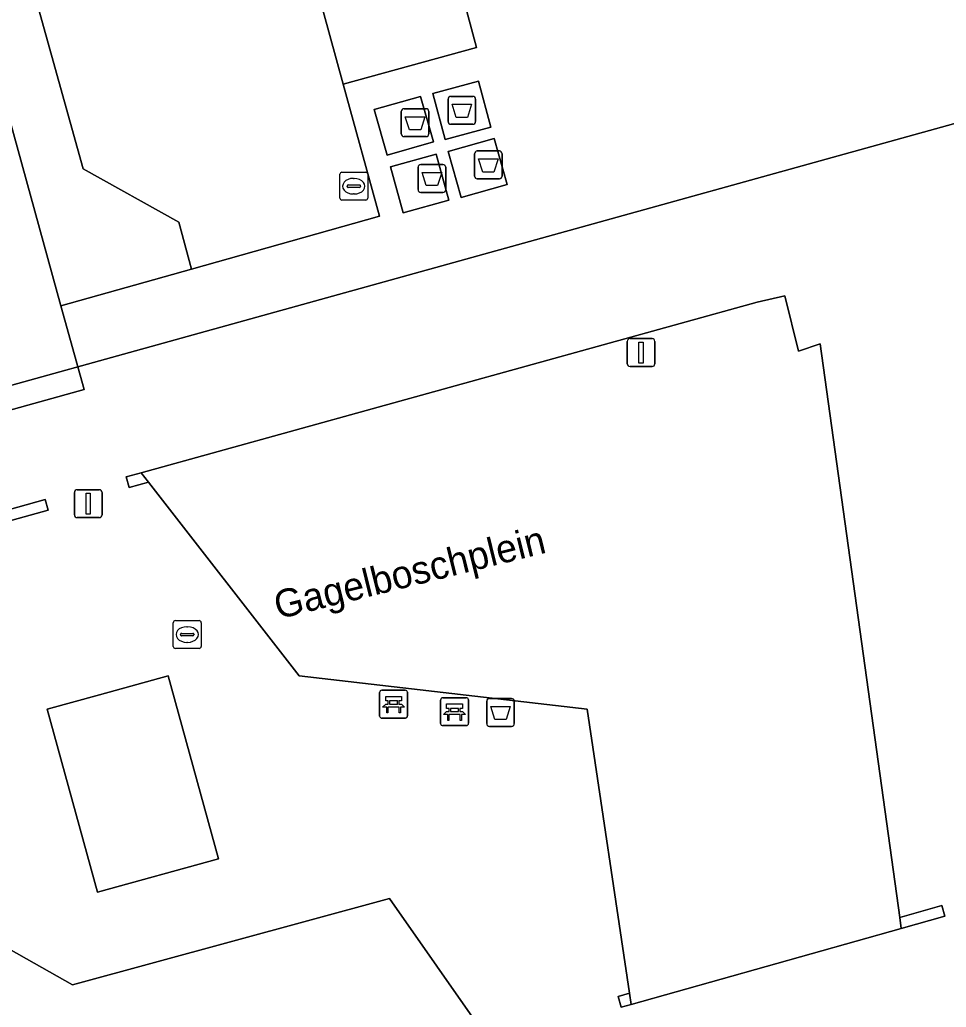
# Model space of a CAD drawing. Extents: x 159053 to 160042, y 380449 to 381423.
# Drawn here: x 159156.36 to 159189.59, y 381123.1 to 381158.52 of the extents above; entities that cross this region are included whole.
import ezdxf

# ---------------------------------------------------------------- set-up
doc = ezdxf.new("R2010")
doc.units = 0
for name, color, linetype in [('IMGEO_Afval_apart_plaats', 7, 'Continuous'), ('IMGEO_Afvalbak', 7, 'Continuous'), ('IMGEO_Bank', 7, 'Continuous'), ('IMGEO_Brandkraan', 7, 'Continuous'), ('IMGEO_Groenvoorziening', 7, 'Continuous'), ('IMGEO_Lichtmast', 7, 'Continuous'), ('IMGEO_Muur', 7, 'Continuous'), ('IMGEO_Openbare_ruimte_label', 7, 'Continuous'), ('IMGEO_Pand', 7, 'Continuous'), ('IMGEO_Pand_overbouw', 7, 'Continuous'), ('IMGEO_Pand_vergunning_verleend', 7, 'Continuous'), ('IMGEO_Parkeervlak_open', 7, 'Continuous'), ('IMGEO_Rijbaan_lokaal_open', 7, 'Continuous'), ('IMGEO_Voetpad_gesloten', 7, 'Continuous'), ('IMGEO_Voetpad_open', 7, 'Continuous')]:
    doc.layers.add(name, color=color, linetype=linetype)

msp = doc.modelspace()

# ---------------------------------------------------------------- linework, layer by layer
at = {"layer": 'IMGEO_Afval_apart_plaats'}
for p, q in [((159171.819, 381155.769), (159172.609, 381155.769)), ((159172.609, 381155.769), (159171.819, 381155.769)), ((159171.719, 381154.869), (159171.719, 381155.669)), ((159171.719, 381155.669), (159171.719, 381154.869)), ((159172.709, 381155.669), (159172.709, 381154.869)), ((159172.709, 381154.869), (159172.709, 381155.669)), ((159170.041, 381154.425), (159170.041, 381155.225)), ((159170.041, 381155.225), (159170.041, 381154.425)), ((159170.141, 381155.325), (159170.931, 381155.325)), ((159170.931, 381155.325), (159170.141, 381155.325)), ((159171.031, 381155.225), (159171.031, 381154.425)), ((159171.031, 381154.425), (159171.031, 381155.225)), ((159172.609, 381154.769), (159171.819, 381154.769)), ((159171.819, 381154.769), (159172.609, 381154.769)), ((159170.931, 381154.325), (159170.141, 381154.325)), ((159170.141, 381154.325), (159170.931, 381154.325)), ((159172.669, 381152.91), (159172.669, 381153.71)), ((159172.669, 381153.71), (159172.669, 381152.91)), ((159172.769, 381153.81), (159173.559, 381153.81)), ((159173.559, 381153.81), (159172.769, 381153.81)), ((159173.659, 381153.71), (159173.659, 381152.91)), ((159173.659, 381152.91), (159173.659, 381153.71)), ((159170.645, 381152.424), (159170.645, 381153.224)), ((159170.645, 381153.224), (159170.645, 381152.424)), ((159170.745, 381153.324), (159171.535, 381153.324)), ((159171.535, 381153.324), (159170.745, 381153.324)), ((159171.635, 381153.224), (159171.635, 381152.424)), ((159171.635, 381152.424), (159171.635, 381153.224)), ((159173.559, 381152.81), (159172.769, 381152.81)), ((159172.769, 381152.81), (159173.559, 381152.81)), ((159171.535, 381152.324), (159170.745, 381152.324)), ((159170.745, 381152.324), (159171.535, 381152.324))]:
    msp.add_line(p, q, dxfattribs=at)
for points in [[(159171.862, 381155.483), (159172.566, 381155.483), (159172.417, 381155.013), (159172.011, 381155.013), (159171.862, 381155.483)], [(159170.184, 381155.039), (159170.888, 381155.039), (159170.739, 381154.569), (159170.333, 381154.569), (159170.184, 381155.039)], [(159172.812, 381153.524), (159173.516, 381153.524), (159173.367, 381153.054), (159172.961, 381153.054), (159172.812, 381153.524)], [(159170.788, 381153.038), (159171.492, 381153.038), (159171.343, 381152.568), (159170.937, 381152.568), (159170.788, 381153.038)]]:
    msp.add_lwpolyline(points, dxfattribs=at)
for centre, start, end in [((159171.819, 381155.669), 90, 180), ((159171.819, 381155.669), 90, 180), ((159172.609, 381155.669), 0, 90), ((159172.609, 381155.669), 360, 90), ((159170.141, 381155.225), 90, 180), ((159170.141, 381155.225), 90, 180), ((159170.931, 381155.225), 0, 90), ((159170.931, 381155.225), 360, 90), ((159171.819, 381154.869), 180, 270), ((159171.819, 381154.869), 180, 270), ((159172.609, 381154.869), 270, 0), ((159172.609, 381154.869), 270, 0), ((159170.141, 381154.425), 180, 270), ((159170.141, 381154.425), 180, 270), ((159170.931, 381154.425), 270, 0), ((159170.931, 381154.425), 270, 0), ((159172.769, 381153.71), 90, 180), ((159172.769, 381153.71), 90, 180), ((159173.559, 381153.71), 0, 90), ((159173.559, 381153.71), 360, 90), ((159170.745, 381153.224), 90, 180), ((159170.745, 381153.224), 90, 180), ((159171.535, 381153.224), 0, 90), ((159171.535, 381153.224), 360, 90), ((159172.769, 381152.91), 180, 270), ((159172.769, 381152.91), 180, 270), ((159173.559, 381152.91), 270, 0), ((159173.559, 381152.91), 270, 0), ((159170.745, 381152.424), 180, 270), ((159170.745, 381152.424), 180, 270), ((159171.535, 381152.424), 270, 0), ((159171.535, 381152.424), 270, 0)]:
    msp.add_arc(centre, 0.1, start, end, dxfattribs=at)
at = {"layer": 'IMGEO_Afvalbak'}
for p, q in [((159173.206, 381134.175), (159173.996, 381134.175)), ((159173.996, 381134.175), (159173.206, 381134.175)), ((159173.106, 381133.275), (159173.106, 381134.075)), ((159173.106, 381134.075), (159173.106, 381133.275)), ((159174.096, 381134.075), (159174.096, 381133.275)), ((159174.096, 381133.275), (159174.096, 381134.075)), ((159173.996, 381133.175), (159173.206, 381133.175)), ((159173.206, 381133.175), (159173.996, 381133.175))]:
    msp.add_line(p, q, dxfattribs=at)
msp.add_lwpolyline([(159173.249, 381133.889), (159173.953, 381133.889), (159173.804, 381133.419), (159173.398, 381133.419), (159173.249, 381133.889)], dxfattribs=at)
for centre, start, end in [((159173.206, 381134.075), 90, 180), ((159173.206, 381134.075), 90, 180), ((159173.996, 381134.075), 0, 90), ((159173.996, 381134.075), 360, 90), ((159173.206, 381133.275), 180, 270), ((159173.206, 381133.275), 180, 270), ((159173.996, 381133.275), 270, 0), ((159173.996, 381133.275), 270, 0)]:
    msp.add_arc(centre, 0.1, start, end, dxfattribs=at)
at = {"layer": 'IMGEO_Bank'}
for p, q in [((159169.34, 381134.471), (159170.181, 381134.471)), ((159170.181, 381134.471), (159169.34, 381134.471)), ((159169.265, 381133.546), (159169.265, 381134.387)), ((159169.265, 381134.387), (159169.265, 381133.546)), ((159169.906, 381134.089), (159169.624, 381134.089)), ((159170.265, 381134.396), (159170.265, 381133.555)), ((159170.265, 381133.555), (159170.265, 381134.396)), ((159171.452, 381133.278), (159171.452, 381134.119)), ((159171.452, 381134.119), (159171.452, 381133.278)), ((159171.527, 381134.203), (159172.368, 381134.203)), ((159172.368, 381134.203), (159171.527, 381134.203)), ((159172.452, 381134.128), (159172.452, 381133.287)), ((159172.452, 381133.287), (159172.452, 381134.128)), ((159169.962, 381133.869), (159169.569, 381133.869)), ((159169.574, 381133.977), (159169.574, 381134.083)), ((159169.618, 381134.083), (159169.618, 381133.977)), ((159169.624, 381133.971), (159169.906, 381133.971)), ((159169.912, 381133.977), (159169.912, 381134.083)), ((159169.956, 381134.083), (159169.956, 381133.977)), ((159171.761, 381133.709), (159171.761, 381133.815)), ((159171.805, 381133.815), (159171.805, 381133.709)), ((159172.093, 381133.821), (159171.811, 381133.821)), ((159172.099, 381133.709), (159172.099, 381133.815)), ((159172.143, 381133.815), (159172.143, 381133.709)), ((159170.19, 381133.471), (159169.349, 381133.471)), ((159169.349, 381133.471), (159170.19, 381133.471)), ((159172.149, 381133.601), (159171.756, 381133.601)), ((159171.811, 381133.703), (159172.093, 381133.703)), ((159172.377, 381133.203), (159171.536, 381133.203)), ((159171.536, 381133.203), (159172.377, 381133.203))]:
    msp.add_line(p, q, dxfattribs=at)
for points in [[(159169.568, 381134.089), (159169.482, 381134.089), (159169.482, 381134.25), (159170.045, 381134.25), (159170.045, 381134.089), (159169.962, 381134.089)], [(159169.512, 381133.869), (159169.37, 381133.869), (159169.482, 381133.971), (159169.568, 381133.971)], [(159169.562, 381133.862), (159169.562, 381133.655), (159169.519, 381133.655), (159169.519, 381133.862)], [(159169.962, 381133.971), (159170.045, 381133.971), (159170.157, 381133.869), (159170.018, 381133.869)], [(159170.012, 381133.862), (159170.012, 381133.655), (159169.968, 381133.655), (159169.968, 381133.862)], [(159171.755, 381133.821), (159171.669, 381133.821), (159171.669, 381133.982), (159172.232, 381133.982), (159172.232, 381133.821), (159172.149, 381133.821)], [(159171.699, 381133.601), (159171.557, 381133.601), (159171.669, 381133.703), (159171.755, 381133.703)], [(159171.749, 381133.594), (159171.749, 381133.387), (159171.706, 381133.387), (159171.706, 381133.594)], [(159172.149, 381133.703), (159172.232, 381133.703), (159172.344, 381133.601), (159172.205, 381133.601)], [(159172.199, 381133.594), (159172.199, 381133.387), (159172.155, 381133.387), (159172.155, 381133.594)]]:
    msp.add_lwpolyline(points, dxfattribs=at)
for centre, radius, start, end in [((159169.343, 381134.393), 0.0779, 92.4484, 184.2845), ((159169.343, 381134.393), 0.0779, 92.4484, 184.2845), ((159170.187, 381134.393), 0.0779, 2.4484, 94.2845), ((159170.187, 381134.393), 0.0779, 2.4484, 94.2845), ((159169.567, 381134.082), 0.00671, 2.8957, 87.1043), ((159169.624, 381134.082), 0.00671, 92.8957, 177.1043), ((159169.906, 381134.082), 0.00671, 2.8957, 87.1043), ((159169.963, 381134.082), 0.00671, 92.8957, 177.1043), ((159171.53, 381134.125), 0.0779, 92.4484, 184.2845), ((159171.53, 381134.125), 0.0779, 92.4484, 184.2845), ((159172.374, 381134.125), 0.0779, 2.4484, 94.2845), ((159172.374, 381134.125), 0.0779, 2.4484, 94.2845), ((159169.512, 381133.862), 0.00671, 2.8957, 87.1043), ((159169.569, 381133.862), 0.00671, 92.8957, 177.1043), ((159169.567, 381133.978), 0.00671, 272.8957, 357.1043), ((159169.624, 381133.978), 0.00671, 182.8957, 267.1043), ((159169.906, 381133.978), 0.00671, 272.8957, 357.1043), ((159169.963, 381133.978), 0.00671, 182.8957, 267.1043), ((159169.961, 381133.862), 0.00671, 2.8957, 87.1043), ((159170.018, 381133.862), 0.00671, 92.8957, 177.1043), ((159171.754, 381133.814), 0.00671, 2.8957, 87.1043), ((159171.811, 381133.814), 0.00671, 92.8957, 177.1043), ((159172.093, 381133.814), 0.00671, 2.8957, 87.1043), ((159172.15, 381133.814), 0.00671, 92.8957, 177.1043), ((159169.343, 381133.549), 0.0779, 182.4484, 274.2845), ((159169.343, 381133.549), 0.0779, 182.4484, 274.2845), ((159170.187, 381133.549), 0.0779, 272.4484, 4.2845), ((159170.187, 381133.549), 0.0779, 272.4484, 4.2845), ((159171.699, 381133.594), 0.00671, 2.8957, 87.1043), ((159171.756, 381133.594), 0.00671, 92.8957, 177.1043), ((159171.754, 381133.71), 0.00671, 272.8957, 357.1043), ((159171.811, 381133.71), 0.00671, 182.8957, 267.1043), ((159172.093, 381133.71), 0.00671, 272.8957, 357.1043), ((159172.15, 381133.71), 0.00671, 182.8957, 267.1043), ((159172.148, 381133.594), 0.00671, 2.8957, 87.1043), ((159172.205, 381133.594), 0.00671, 92.8957, 177.1043), ((159171.53, 381133.281), 0.0779, 182.4484, 274.2845), ((159171.53, 381133.281), 0.0779, 182.4484, 274.2845), ((159172.374, 381133.281), 0.0779, 272.4484, 4.2845), ((159172.374, 381133.281), 0.0779, 272.4484, 4.2845)]:
    msp.add_arc(centre, radius, start, end, dxfattribs=at)
at = {"layer": 'IMGEO_Brandkraan'}
for p, q in [((159167.838, 381152.121), (159167.838, 381152.973)), ((159167.913, 381153.047), (159168.765, 381153.047)), ((159168.839, 381152.973), (159168.839, 381152.121)), ((159168.097, 381152.541), (159168.097, 381152.553)), ((159168.535, 381152.504), (159168.137, 381152.504)), ((159168.14, 381152.59), (159168.538, 381152.59)), ((159168.326, 381152.827), (159168.351, 381152.827)), ((159168.581, 381152.553), (159168.581, 381152.541)), ((159168.349, 381152.267), (159168.324, 381152.267)), ((159168.765, 381152.047), (159167.913, 381152.047)), ((159161.939, 381136.968), (159162.791, 381136.968)), ((159161.864, 381136.042), (159161.864, 381136.894)), ((159162.352, 381136.748), (159162.377, 381136.748)), ((159162.865, 381136.894), (159162.865, 381136.042)), ((159162.123, 381136.462), (159162.123, 381136.474)), ((159162.561, 381136.425), (159162.163, 381136.425)), ((159162.166, 381136.511), (159162.564, 381136.511)), ((159162.607, 381136.474), (159162.607, 381136.462)), ((159162.791, 381135.968), (159161.939, 381135.968)), ((159162.375, 381136.188), (159162.35, 381136.188))]:
    msp.add_line(p, q, dxfattribs=at)
for points in [[(159167.838, 381152.121), (159167.838, 381152.973)], [(159167.913, 381153.047), (159168.765, 381153.047)], [(159168.839, 381152.973), (159168.839, 381152.121)], [(159168.765, 381152.047), (159167.913, 381152.047)], [(159161.939, 381136.968), (159162.791, 381136.968)], [(159161.864, 381136.042), (159161.864, 381136.894)], [(159162.865, 381136.894), (159162.865, 381136.042)], [(159162.791, 381135.968), (159161.939, 381135.968)]]:
    msp.add_lwpolyline(points, dxfattribs=at)
for centre, radius, start, end in [((159167.915, 381152.971), 0.0765, 91.552, 178.448), ((159167.915, 381152.971), 0.0765, 91.552, 178.448), ((159168.763, 381152.971), 0.0765, 1.552, 88.448), ((159168.763, 381152.971), 0.0765, 1.552, 88.448), ((159168.137, 381152.55), 0.0403, 85.8775, 175.7526), ((159168.134, 381152.54), 0.0366, 178.938, 274.7102), ((159168.538, 381152.547), 0.043, 264.8664, 352.4533), ((159168.542, 381152.552), 0.0386, 1.7309, 96.639), ((159167.915, 381152.123), 0.0765, 181.552, 268.448), ((159167.915, 381152.123), 0.0765, 181.552, 268.448), ((159168.763, 381152.123), 0.0765, 271.552, 358.448), ((159168.763, 381152.123), 0.0765, 271.552, 358.448), ((159161.941, 381136.892), 0.0765, 91.552, 178.448), ((159161.941, 381136.892), 0.0765, 91.552, 178.448), ((159162.789, 381136.892), 0.0765, 1.552, 88.448), ((159162.789, 381136.892), 0.0765, 1.552, 88.448), ((159162.163, 381136.471), 0.0403, 85.8775, 175.7526), ((159162.16, 381136.461), 0.0366, 178.938, 274.7102), ((159162.564, 381136.468), 0.043, 264.8664, 352.4533), ((159162.568, 381136.473), 0.0386, 1.7309, 96.639), ((159161.941, 381136.044), 0.0765, 181.552, 268.448), ((159161.941, 381136.044), 0.0765, 181.552, 268.448), ((159162.789, 381136.044), 0.0765, 271.552, 358.448), ((159162.789, 381136.044), 0.0765, 271.552, 358.448)]:
    msp.add_arc(centre, radius, start, end, dxfattribs=at)
for centre, major_axis, ratio, start_param, end_param in [((159168.325, 381152.547), (-0.387, 0.002), 0.722429, 4.712389, 7.853982), ((159168.35, 381152.547), (-0.39, 0.002), 0.717154, 1.570796, 4.712389), ((159162.351, 381136.468), (-0.387, 0.002), 0.722429, 4.712389, 7.853982), ((159162.376, 381136.468), (-0.39, 0.002), 0.717154, 1.570796, 4.712389)]:
    msp.add_ellipse(centre, major_axis=major_axis, ratio=ratio, start_param=start_param, end_param=end_param, dxfattribs=at)
at = {"layer": 'IMGEO_Groenvoorziening'}
msp.add_lwpolyline([(159121.982, 381156.173), (159127.859, 381157.764), (159125.308, 381167.186), (159149.74, 381174.045), (159151.875, 381166.058), (159152.853, 381166.328), (159154.809, 381166.867), (159158.633, 381153.175), (159162.065, 381151.254), (159162.515, 381149.573), (159169.259, 381151.47), (159167.96, 381156.207), (159163.076, 381174.02), (159172.151, 381181.759)], dxfattribs=at)
for points in [[(159185.063, 381146.894), (159184.287, 381146.632), (159183.8, 381148.611), (159182.803, 381148.391), (159160.708, 381142.27), (159160.973, 381141.929), (159166.375, 381134.982), (159176.706, 381133.787), (159178.227, 381123.602), (159178.286, 381123.204), (159187.976, 381125.924), (159187.92, 381126.324)], [(159173.017, 381122.146), (159169.622, 381127.006), (159158.252, 381123.901), (159154.58, 381125.969), (159142.499, 381121.107), (159142.126, 381120.957), (159144.125, 381113.742), (159173.26, 381121.799)]]:
    msp.add_lwpolyline(points, close=True, dxfattribs=at)
at = {"layer": 'IMGEO_Lichtmast'}
for p, q in [((159178.147, 381146.181), (159178.147, 381146.981)), ((159178.147, 381146.981), (159178.147, 381146.181)), ((159178.247, 381147.081), (159179.037, 381147.081)), ((159179.037, 381147.081), (159178.247, 381147.081)), ((159179.137, 381146.981), (159179.137, 381146.181)), ((159179.137, 381146.181), (159179.137, 381146.981)), ((159179.037, 381146.081), (159178.247, 381146.081)), ((159178.247, 381146.081), (159179.037, 381146.081)), ((159158.318, 381140.763), (159158.318, 381141.563)), ((159158.318, 381141.563), (159158.318, 381140.763)), ((159158.418, 381141.663), (159159.208, 381141.663)), ((159159.208, 381141.663), (159158.418, 381141.663)), ((159159.308, 381141.563), (159159.308, 381140.763)), ((159159.308, 381140.763), (159159.308, 381141.563)), ((159159.208, 381140.663), (159158.418, 381140.663)), ((159158.418, 381140.663), (159159.208, 381140.663))]:
    msp.add_line(p, q, dxfattribs=at)
for points in [[(159178.567, 381146.956), (159178.717, 381146.956), (159178.717, 381146.206), (159178.567, 381146.206), (159178.567, 381146.956)], [(159158.738, 381141.538), (159158.888, 381141.538), (159158.888, 381140.788), (159158.738, 381140.788), (159158.738, 381141.538)]]:
    msp.add_lwpolyline(points, dxfattribs=at)
for centre, start, end in [((159178.247, 381146.981), 90, 180), ((159178.247, 381146.981), 90, 180), ((159179.037, 381146.981), 0, 90), ((159179.037, 381146.981), 360, 90), ((159178.247, 381146.181), 180, 270), ((159178.247, 381146.181), 180, 270), ((159179.037, 381146.181), 270, 0), ((159179.037, 381146.181), 270, 0), ((159158.418, 381141.563), 90, 180), ((159158.418, 381141.563), 90, 180), ((159159.208, 381141.563), 0, 90), ((159159.208, 381141.563), 360, 90), ((159158.418, 381140.763), 180, 270), ((159158.418, 381140.763), 180, 270), ((159159.208, 381140.763), 270, 0), ((159159.208, 381140.763), 270, 0)]:
    msp.add_arc(centre, 0.1, start, end, dxfattribs=at)
at = {"layer": 'IMGEO_Muur'}
for points in [[(159160.708, 381142.27), (159160.178, 381142.122), (159160.285, 381141.737), (159160.973, 381141.929)], [(159154.567, 381140.146), (159157.376, 381140.928), (159157.269, 381141.313), (159154.608, 381140.573)], [(159187.976, 381125.924), (159189.542, 381126.364), (159189.434, 381126.749), (159187.92, 381126.324)], [(159178.227, 381123.602), (159177.82, 381123.488), (159177.928, 381123.103), (159178.286, 381123.204)]]:
    msp.add_lwpolyline(points, close=True, dxfattribs=at)
at = {"layer": 'IMGEO_Pand'}
msp.add_lwpolyline([(159161.678, 381134.985), (159159.218, 381134.307), (159157.337, 381133.789), (159159.144, 381127.23), (159163.485, 381128.427)], close=True, dxfattribs=at)
at = {"layer": 'IMGEO_Pand_overbouw'}
msp.add_lwpolyline([(159249.617, 381146.417), (159253.067, 381147.375), (159252.059, 381151.007), (159248.609, 381150.05), (159244.524, 381164.774), (159216.821, 381157.087), (159215.484, 381161.905), (159146.712, 381142.823), (159144.149, 381142.112), (159127.074, 381137.375), (159127.322, 381136.481), (159127.96, 381134.183), (159128.847, 381130.986), (159129.855, 381127.353), (159132.702, 381117.091), (159133.413, 381114.528), (159135.79, 381105.961), (159251.903, 381138.179)], close=True, dxfattribs=at)
at = {"layer": 'IMGEO_Pand_vergunning_verleend'}
msp.add_lwpolyline([(159251.903, 381138.179), (159135.79, 381105.961), (159133.413, 381114.528), (159130.137, 381113.619), (159129.426, 381116.182), (159132.702, 381117.091), (159129.855, 381127.353), (159126.405, 381126.396), (159125.397, 381130.029), (159128.847, 381130.986), (159127.074, 381137.375), (159144.149, 381142.112), (159143.24, 381145.388), (159145.803, 381146.1), (159146.712, 381142.823), (159215.484, 381161.905), (159216.821, 381157.087), (159244.524, 381164.774), (159248.609, 381150.05), (159252.059, 381151.007), (159253.067, 381147.375), (159249.617, 381146.417)], close=True, dxfattribs=at)
at = {"layer": 'IMGEO_Parkeervlak_open'}
msp.add_lwpolyline([(159175.262, 381178.12), (159172.151, 381181.759), (159163.076, 381174.02), (159167.96, 381156.207), (159172.738, 381157.517), (159168.774, 381172.342), (159169.083, 381172.617)], close=True, dxfattribs=at)
at = {"layer": 'IMGEO_Rijbaan_lokaal_open'}
msp.add_lwpolyline([(159168.774, 381172.342), (159172.738, 381157.517), (159167.96, 381156.207), (159169.259, 381151.47), (159162.515, 381149.573), (159157.836, 381148.256), (159158.67, 381145.252), (159127.838, 381136.682)], dxfattribs=at)
for points in [[(159173.254, 381154.667), (159171.619, 381154.225), (159171.174, 381155.871), (159172.809, 381156.313)], [(159171.199, 381154.132), (159169.535, 381153.662), (159169.073, 381155.297), (159170.737, 381155.767)], [(159173.835, 381152.606), (159172.186, 381152.139), (159171.719, 381153.788), (159173.368, 381154.255)], [(159171.748, 381152.043), (159170.11, 381151.595), (159169.659, 381153.245), (159171.297, 381153.693)], [(159187.92, 381126.324), (159189.434, 381126.749), (159189.542, 381126.364), (159187.976, 381125.924), (159178.286, 381123.204), (159177.928, 381123.103), (159177.82, 381123.488), (159178.227, 381123.602), (159176.706, 381133.787), (159166.375, 381134.982), (159160.973, 381141.929), (159160.285, 381141.737), (159160.178, 381142.122), (159160.708, 381142.27), (159182.803, 381148.391), (159183.8, 381148.611), (159184.287, 381146.632), (159185.063, 381146.894)], [(159153.521, 381129.277), (159141.196, 381125.842), (159141.428, 381125.001), (159141.043, 381124.894), (159140.81, 381125.734), (159137.983, 381135.948), (159154.608, 381140.573), (159157.269, 381141.313), (159157.376, 381140.928), (159154.567, 381140.146)], [(159163.485, 381128.427), (159159.144, 381127.23), (159157.337, 381133.789), (159159.218, 381134.307), (159161.678, 381134.985)], [(159173.017, 381122.146), (159174.032, 381122.427), (159174.138, 381122.041), (159173.26, 381121.799), (159144.125, 381113.742), (159142.126, 381120.957), (159141.872, 381121.873), (159142.257, 381121.98), (159142.499, 381121.107), (159154.58, 381125.969), (159158.252, 381123.901), (159169.622, 381127.006)]]:
    msp.add_lwpolyline(points, close=True, dxfattribs=at)
at = {"layer": 'IMGEO_Voetpad_gesloten'}
for points in [[(159172.809, 381156.313), (159171.174, 381155.871), (159171.619, 381154.225), (159173.254, 381154.667)], [(159170.737, 381155.767), (159169.073, 381155.297), (159169.535, 381153.662), (159171.199, 381154.132)], [(159173.368, 381154.255), (159171.719, 381153.788), (159172.186, 381152.139), (159173.835, 381152.606)], [(159171.297, 381153.693), (159169.659, 381153.245), (159170.11, 381151.595), (159171.748, 381152.043)]]:
    msp.add_lwpolyline(points, close=True, dxfattribs=at)
at = {"layer": 'IMGEO_Voetpad_open'}
for points in [[(159158.67, 381145.252), (159157.836, 381148.256), (159152.853, 381166.328), (159151.875, 381166.058), (159149.74, 381174.045), (159125.308, 381167.186), (159127.859, 381157.764), (159130.025, 381158.35), (159128.03, 381165.753), (159148.439, 381171.433), (159150.512, 381163.915), (159150.446, 381163.897), (159155.464, 381145.813), (159135.221, 381140.226), (159134.583, 381142.54), (159123.394, 381139.418), (159123.313, 381139.396), (159124.153, 381136.349), (159124.172, 381136.281)], [(159172.192, 381030.266), (159168.355, 381029.191), (159166.428, 381036.194), (159165.838, 381038.326), (159160.631, 381057.094), (159160.173, 381058.899), (159151.749, 381089.223), (159151.24, 381091.03), (159149.2, 381098.326), (159146.475, 381107.584), (159144.715, 381107.11), (159149.107, 381091.316), (159140.461, 381088.976), (159139.241, 381093.58), (159136.841, 381102.636), (159137.458, 381102.8), (159136.865, 381104.934), (159130.021, 381129.568), (159129.403, 381131.055), (159127.838, 381136.682), (159158.67, 381145.252)]]:
    msp.add_lwpolyline(points, dxfattribs=at)
msp.add_lwpolyline([(159152.853, 381166.328), (159157.836, 381148.256), (159162.515, 381149.573), (159162.065, 381151.254), (159158.633, 381153.175), (159154.809, 381166.867)], close=True, dxfattribs=at)

# ---------------------------------------------------------------- texts
at = {"layer": 'IMGEO_Openbare_ruimte_label'}
msp.add_text('Gagelboschplein', height=1, rotation=13.939, dxfattribs=at).set_placement((159165.623, 381137.012))

doc.saveas('drawing.dxf')
